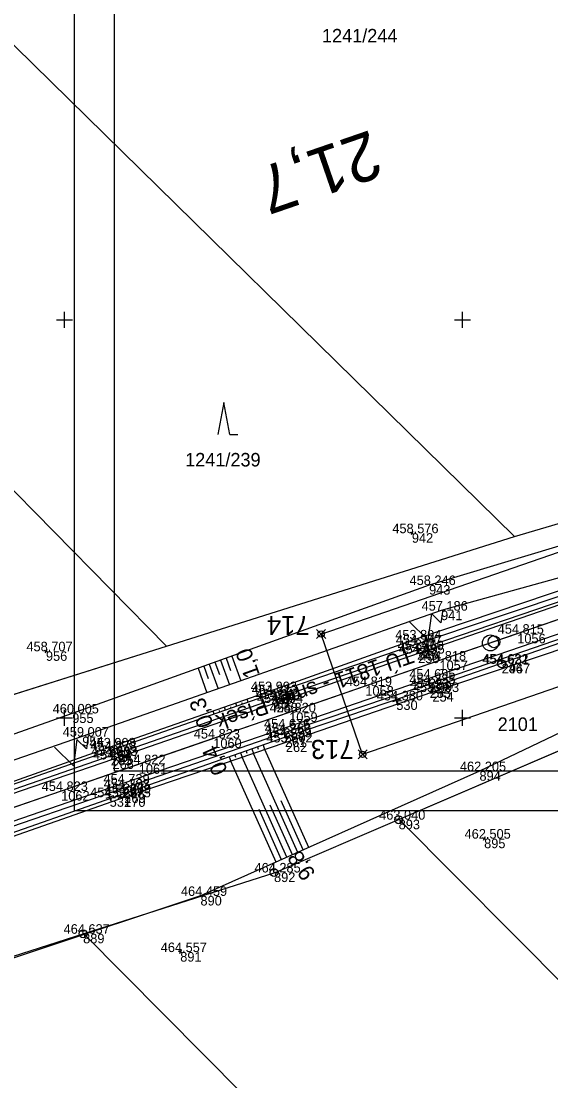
# Model space of a CAD drawing. Extents: x -776734 to -748832, y -1118122 to -976986.
# Drawn here: x -751355.4 to -751288.9, y -1114795.6 to -1114662.5 of the extents above; entities that cross this region are included whole.
import ezdxf

# ---------------------------------------------------------------- set-up
doc = ezdxf.new("R2010")
doc.units = 0
for name, color, linetype in [('KM_Hranice parcel', 7, 'Continuous'), ('KM_Parcelní čísla', 7, 'Continuous'), ('KM_Značky kultur', 7, 'Continuous'), ('Legenda 1 rámy + tabulka + severka', 7, 'Continuous'), ('Level 61 Křížky', 7, 'Continuous'), ('Obvod stavby - SŽ+ČD', 7, 'Continuous'), ('OSA', 7, 'Continuous'), ('SŽG Vrstva 1', 7, 'Continuous'), ('SŽG Vrstva 4', 7, 'Continuous'), ('SŽG Vrstva 48', 7, 'Continuous'), ('SŽG Vrstva 49', 7, 'Continuous'), ('SŽG Vrstva 50', 7, 'Continuous'), ('SŽG Vrstva 53', 7, 'Continuous'), ('SŽG Vrstva 60', 7, 'Continuous'), ('SŽG Vrstva 61', 7, 'Continuous'), ('SŽG Vrstva 7', 7, 'Continuous'), ('VYT-BODY', 7, 'Continuous')]:
    doc.layers.add(name, color=color, linetype=linetype)

msp = doc.modelspace()

# ---------------------------------------------------------------- linework, layer by layer
at = {"layer": 'KM_Hranice parcel'}
for p, q in [((-751293.44, -1114727.24), (-751406.13, -1114616.64)), ((-751439.38, -1114637.08), (-751337.18, -1114740.99)), ((-751337.18, -1114740.99), (-751293.44, -1114727.24)), ((-751377.2, -1114753.63), (-751337.18, -1114740.99)), ((-751268.46, -1114745.82), (-751307.93, -1114762.77))]:
    msp.add_line(p, q, dxfattribs=at)
for points in [[(-751293.44, -1114727.24), (-751276.39, -1114722.19), (-751236.9, -1114707.02)], [(-751307.93, -1114762.77), (-751323.57, -1114769.49), (-751347.57, -1114777.14)], [(-751307.93, -1114762.77), (-751286.55, -1114784.31), (-751238.76, -1114832.46), (-751161.13, -1114910.68), (-751116.44, -1114955.71)], [(-751347.57, -1114777.14), (-751364.44, -1114782.53), (-751398.43, -1114791.82)], [(-751126.76, -1114999.86), (-751195.24, -1114930.79), (-751259.42, -1114866.05), (-751317.55, -1114807.42), (-751347.57, -1114777.14)]]:
    msp.add_lwpolyline(points, dxfattribs=at)
at = {"layer": 'KM_Značky kultur'}
for p, q in [((-751329.9624, -1114710.4091), (-751330.7124, -1114714.4091)), ((-751329.2124, -1114714.4091), (-751329.9624, -1114710.4091)), ((-751329.2124, -1114714.4091), (-751328.2164, -1114714.4091))]:
    msp.add_line(p, q, dxfattribs=at)
at = {"layer": 'Legenda 1 rámy + tabulka + severka'}
for p, q in [((-751343.7143, -1114756.7085), (-751343.7143, -1114346.7085)), ((-751348.7143, -1114761.7085), (-751348.7143, -1114551.7085)), ((-751051.7143, -1114756.7085), (-751343.7143, -1114756.7085)), ((-751051.7143, -1114761.7085), (-751348.7143, -1114761.7085)), ((-751051.7143, -1114761.7085), (-751348.7143, -1114761.7085)), ((-751051.7143, -1114761.7085), (-751348.7143, -1114761.7085))]:
    msp.add_line(p, q, dxfattribs=at)
at = {"layer": 'Level 61 Křížky'}
for p, q in [((-751350, -1114700), (-751350, -1114699)), ((-751300, -1114700), (-751300, -1114699)), ((-751351, -1114700), (-751349, -1114700)), ((-751350, -1114701), (-751350, -1114700)), ((-751301, -1114700), (-751299, -1114700)), ((-751300, -1114701), (-751300, -1114700)), ((-751351, -1114750), (-751349, -1114750)), ((-751350, -1114750), (-751350, -1114749)), ((-751350, -1114751), (-751350, -1114750)), ((-751301, -1114750), (-751299, -1114750)), ((-751300, -1114750), (-751300, -1114749)), ((-751300, -1114751), (-751300, -1114750))]:
    msp.add_line(p, q, dxfattribs=at)
at = {"layer": 'Obvod stavby - SŽ+ČD'}
msp.add_lwpolyline([(-751172.58, -1114730.25), (-751213.65, -1114726.85), (-751218.67, -1114726.44), (-751238.9319, -1114729.2086), (-751312.5308, -1114754.601), (-751317.7491, -1114739.4759), (-751244.1502, -1114714.0835), (-751236.9, -1114707.02), (-751193.03, -1114664.28)], dxfattribs=at)
at = {"layer": 'OSA'}
for p, q in [((-751221.2446, -1114714.6435), (-751305.6868, -1114743.777)), ((-751305.6868, -1114743.777), (-751648.6661, -1114862.1099))]:
    msp.add_line(p, q, dxfattribs=at)
msp.add_circle((-751296.4756, -1114740.599), 1, dxfattribs=at)
at = {"layer": 'SŽG Vrstva 1'}
msp.add_lwpolyline([(-751207.289, -1114709.832), (-751216.509, -1114713.014), (-751226.434, -1114716.437), (-751236.324, -1114719.849), (-751245.849, -1114723.137), (-751255.285, -1114726.393), (-751264.701, -1114729.644), (-751273.956, -1114732.837), (-751283.458, -1114736.112), (-751293.108, -1114739.442), (-751302.881, -1114742.811), (-751312.192, -1114746.024), (-751321.757, -1114749.321), (-751331.295, -1114752.611), (-751340.65, -1114755.838), (-751350.401, -1114759.203), (-751359.686, -1114762.406)], dxfattribs=at)
at = {"layer": 'SŽG Vrstva 4'}
for points in [[(-751187.894, -1114700.58), (-751206.028, -1114707.041), (-751231.235, -1114715.596), (-751249.544, -1114721.971), (-751267.723, -1114728.471), (-751285.298, -1114734.541), (-751305.686, -1114741.509), (-751323.628, -1114747.668), (-751344.164, -1114754.785), (-751362.443, -1114761.123), (-751382.646, -1114767.996), (-751419.827, -1114780.907), (-751439.841, -1114787.752), (-751459.648, -1114794.565), (-751479.262, -1114801.395), (-751499.563, -1114808.301), (-751517.656, -1114814.613), (-751524.467, -1114817.135), (-751524.911, -1114817.646)], [(-751186.455, -1114705.269), (-751204.57, -1114711.262), (-751229.26, -1114719.967), (-751248.511, -1114726.389), (-751266.031, -1114732.591), (-751283.828, -1114738.73), (-751304.211, -1114745.766), (-751322.374, -1114751.898), (-751342.612, -1114758.897), (-751360.965, -1114765.168), (-751381.114, -1114772.121), (-751418.537, -1114784.997), (-751438.613, -1114791.912), (-751458.172, -1114798.656), (-751477.814, -1114805.419), (-751497.901, -1114812.476), (-751516.513, -1114818.688), (-751522.385, -1114820.606), (-751523.195, -1114820.521)], [(-751205.795, -1114707.603), (-751230.97, -1114716.264), (-751249.417, -1114722.675), (-751267.451, -1114728.869), (-751285.106, -1114734.872), (-751305.56, -1114741.936), (-751323.346, -1114748.135), (-751343.956, -1114755.234), (-751362.406, -1114761.583), (-751382.455, -1114768.543), (-751419.68, -1114781.407), (-751439.787, -1114788.305), (-751459.372, -1114795.057), (-751479.147, -1114801.881), (-751499.337, -1114808.873), (-751517.572, -1114815.159), (-751524.911, -1114817.646)], [(-751204.677, -1114710.75), (-751229.564, -1114719.281), (-751248.527, -1114725.936), (-751266.247, -1114732.037), (-751284.071, -1114738.15), (-751304.213, -1114745.084), (-751322.473, -1114751.338), (-751342.638, -1114758.269), (-751361.135, -1114764.639), (-751381.339, -1114771.707), (-751418.714, -1114784.623), (-751438.728, -1114791.466), (-751458.255, -1114798.22), (-751477.955, -1114804.997), (-751498.184, -1114811.907), (-751516.629, -1114818.238), (-751523.195, -1114820.521)]]:
    msp.add_lwpolyline(points, dxfattribs=at)
at = {"layer": 'SŽG Vrstva 48'}
for p, q in [((-751331.794, -1114743.261), (-751330.675, -1114746.371)), ((-751331.089, -1114743.007), (-751330.528, -1114744.565)), ((-751330.383, -1114742.753), (-751329.26, -1114745.874)), ((-751329.677, -1114742.499), (-751329.115, -1114744.063)), ((-751328.971, -1114742.245), (-751327.844, -1114745.377)), ((-751333.206, -1114743.769), (-751332.09, -1114746.868)), ((-751332.5, -1114743.515), (-751331.941, -1114745.067)), ((-751329.7506, -1114749.0427), (-751329.8823, -1114748.6655)), ((-751329.0425, -1114748.7954), (-751329.1084, -1114748.6068)), ((-751328.3345, -1114748.5481), (-751328.4662, -1114748.1709)), ((-751327.6264, -1114748.3009), (-751327.6923, -1114748.1123)), ((-751326.9183, -1114748.0536), (-751327.0501, -1114747.6764)), ((-751331.1667, -1114749.5373), (-751331.2985, -1114749.16)), ((-751330.4586, -1114749.29), (-751330.5245, -1114749.1014)), ((-751326.4601, -1114753.9138), (-751326.2595, -1114754.4881)), ((-751325.7521, -1114753.6665), (-751325.6507, -1114753.9568)), ((-751325.044, -1114753.4192), (-751324.8391, -1114754.0059)), ((-751319.3023, -1114766.3021), (-751324.8067, -1114753.9948)), ((-751329.2924, -1114754.903), (-751329.1004, -1114755.4526)), ((-751328.5843, -1114754.6557), (-751328.4872, -1114754.9336)), ((-751327.8762, -1114754.4084), (-751327.68, -1114754.9704)), ((-751322.0409, -1114767.5269), (-751327.6598, -1114754.9635)), ((-751327.1682, -1114754.1611), (-751327.069, -1114754.4452)), ((-751320.6716, -1114766.9145), (-751326.2333, -1114754.4792)), ((-751323.4102, -1114768.1394), (-751329.0864, -1114755.4479)), ((-751319.9869, -1114766.6083), (-751322.7535, -1114760.4227)), ((-751322.7255, -1114767.8332), (-751325.5493, -1114761.5194)), ((-751321.3562, -1114767.2207), (-751324.1514, -1114760.9711))]:
    msp.add_line(p, q, dxfattribs=at)
at = {"layer": 'SŽG Vrstva 49'}
for p, q in [((-751306.1203, -1114726.9205), (-751306.5697, -1114726.7015)), ((-751306.2355, -1114726.5863), (-751306.4545, -1114727.0357)), ((-751352.0912, -1114741.7575), (-751352.5408, -1114741.5385)), ((-751352.2065, -1114741.4232), (-751352.4255, -1114741.8728)), ((-751297.0423, -1114765.2965), (-751297.4917, -1114765.0775)), ((-751297.1575, -1114764.9623), (-751297.3765, -1114765.4117)), ((-751335.2193, -1114779.5485), (-751335.6687, -1114779.3295)), ((-751335.3345, -1114779.2143), (-751335.5535, -1114779.6637))]:
    msp.add_line(p, q, dxfattribs=at)
for points in [[(-751234.949, -1114713.279), (-751245.481, -1114717.135), (-751281.469, -1114726.527), (-751304.183, -1114733.326), (-751349.012, -1114749.456), (-751398.203, -1114766.871), (-751445.795, -1114779.905), (-751491.917, -1114801.089), (-751522.469, -1114813.154), (-751523.879, -1114811.232), (-751530.057, -1114804.525)], [(-751231.525, -1114714.481), (-751249.638, -1114721.458), (-751267.891, -1114727.816), (-751285.514, -1114733.952), (-751305.908, -1114740.796), (-751324.002, -1114747.035), (-751344.265, -1114754.112), (-751362.586, -1114760.516), (-751382.595, -1114767.438), (-751402.409, -1114774.045), (-751420.234, -1114780.2), (-751439.893, -1114787.152), (-751459.921, -1114794.045), (-751479.467, -1114800.491), (-751499.785, -1114807.5), (-751517.869, -1114814.102), (-751523.111, -1114815.97), (-751524.209, -1114815.639), (-751526.184, -1114811.436)], [(-751244.9, -1114718.575), (-751249.937, -1114720.628), (-751268.48, -1114726.929), (-751276.661, -1114729.623), (-751285.758, -1114733.326), (-751305.984, -1114740.165), (-751324.128, -1114746.656), (-751344.388, -1114753.731), (-751362.684, -1114760.234), (-751382.771, -1114766.903), (-751402.562, -1114773.563), (-751420.499, -1114779.462), (-751440.12, -1114786.635), (-751460.286, -1114793.369), (-751479.705, -1114799.993), (-751499.94, -1114807.004), (-751518.245, -1114813.43), (-751522.739, -1114814.822), (-751523.674, -1114814.114), (-751524.925, -1114811.322)], [(-751523.899, -1114821.949), (-751516.26, -1114819.366), (-751497.387, -1114813.062), (-751477.616, -1114806.13), (-751458.015, -1114799.124), (-751438.432, -1114792.474), (-751418.478, -1114785.506), (-751400.555, -1114779.532), (-751380.096, -1114772.486), (-751360.669, -1114765.898), (-751342.469, -1114759.505), (-751322.286, -1114752.456), (-751304.11, -1114746.299), (-751283.779, -1114739.207), (-751265.74, -1114733.22), (-751248.287, -1114727.037), (-751240.07, -1114724.297)], [(-751204.754, -1114724.609), (-751227.195, -1114725.505), (-751238.195, -1114726.494), (-751253.205, -1114735.378), (-751297.853, -1114756.709), (-751332.903, -1114772.385), (-751375.498, -1114786.511), (-751400.696, -1114793.558), (-751443.206, -1114803.356), (-751482.539, -1114812.284)], [(-751240.236, -1114725.654), (-751248.02, -1114728.046), (-751265.488, -1114734.037), (-751283.474, -1114739.989), (-751303.76, -1114746.769), (-751322.174, -1114753.101), (-751342.488, -1114759.998), (-751360.52, -1114766.361), (-751379.963, -1114773.044), (-751400.343, -1114780.093), (-751418.294, -1114786.259), (-751438.171, -1114793.174), (-751457.682, -1114799.957), (-751477.222, -1114807.057), (-751497.375, -1114813.972), (-751516.217, -1114820.454), (-751522.915, -1114822.926), (-751523.899, -1114821.949)], [(-751276.661, -1114729.623), (-751280.138, -1114730.299), (-751302.673, -1114736.54), (-751347.758, -1114752.369), (-751397.367, -1114769.54), (-751443.606, -1114786.702), (-751459.316, -1114792.112), (-751460.286, -1114793.369)]]:
    msp.add_lwpolyline(points, dxfattribs=at)
at = {"layer": 'SŽG Vrstva 50'}
for points in [[(-751302.469, -1114736.3918), (-751302.6888, -1114738.0544), (-751303.887, -1114736.881), (-751304.3266, -1114740.2062), (-751306.723, -1114737.8594)], [(-751347.007, -1114752.233), (-751347.227, -1114753.8955), (-751348.425, -1114752.722), (-751348.865, -1114756.0471), (-751351.2611, -1114753.7)]]:
    msp.add_lwpolyline(points, dxfattribs=at)
at = {"layer": 'SŽG Vrstva 53'}
for p, q in [((-751307.9567, -1114762.7917), (-751308.0513, -1114762.8243)), ((-751323.6127, -1114769.4227), (-751323.7073, -1114769.4553)), ((-751347.5967, -1114777.1207), (-751347.6913, -1114777.1533))]:
    msp.add_line(p, q, dxfattribs=at)
for points in [[(-751615.07, -1114840.52), (-751596.62, -1114835), (-751572.02, -1114827.5), (-751551.31, -1114808.23), (-751526.51, -1114811.39), (-751501.68, -1114801.88), (-751460.63, -1114785.23), (-751418.82, -1114768.72), (-751390.21, -1114757.9), (-751377.2, -1114753.63), (-751337.18, -1114740.99), (-751293.44, -1114727.24), (-751276.39, -1114722.19), (-751236.9, -1114707.02), (-751193.03, -1114664.28), (-751178.42, -1114675.26), (-751174.34, -1114678.03), (-751162.9, -1114674.22), (-751118.39, -1114659.47), (-751098.21, -1114652.66), (-751091.59, -1114651.24)], [(-751047.63, -1114693.52), (-751057.9, -1114691.02), (-751081.52, -1114685.27), (-751134.08, -1114703.51), (-751142.83, -1114706.54), (-751153.31, -1114710.17), (-751137.57, -1114746.06), (-751139.06, -1114746.27), (-751138.42, -1114748.17), (-751151.05, -1114751.02), (-751162.24, -1114725.26), (-751172.58, -1114730.25), (-751213.65, -1114726.85), (-751218.67, -1114726.44), (-751268.46, -1114745.82), (-751307.93, -1114762.77), (-751323.57, -1114769.49), (-751347.57, -1114777.14), (-751364.44, -1114782.53)]]:
    msp.add_lwpolyline(points, dxfattribs=at)
for centre in [(-751308.004, -1114762.808), (-751323.66, -1114769.439), (-751347.644, -1114777.137)]:
    msp.add_circle(centre, 0.4993, dxfattribs=at)
at = {"layer": 'SŽG Vrstva 60'}
for p, q in [((-751306.345, -1114726.811), (-751306.345, -1114726.811)), ((-751304.183, -1114733.326), (-751304.183, -1114733.326)), ((-751302.673, -1114736.54), (-751302.673, -1114736.54)), ((-751293.108, -1114739.442), (-751293.108, -1114739.442)), ((-751305.984, -1114740.165), (-751305.984, -1114740.165)), ((-751305.908, -1114740.796), (-751305.908, -1114740.796)), ((-751352.316, -1114741.648), (-751352.316, -1114741.648)), ((-751305.686, -1114741.509), (-751305.686, -1114741.509)), ((-751305.56, -1114741.936), (-751305.56, -1114741.936)), ((-751302.881, -1114742.811), (-751302.881, -1114742.811)), ((-751295.075, -1114743.222), (-751295.075, -1114743.222)), ((-751295.054, -1114743.207), (-751295.054, -1114743.207)), ((-751312.192, -1114746.024), (-751312.192, -1114746.024)), ((-751304.213, -1114745.084), (-751304.213, -1114745.084)), ((-751304.211, -1114745.766), (-751304.211, -1114745.766)), ((-751324.128, -1114746.656), (-751324.128, -1114746.656)), ((-751324.002, -1114747.035), (-751324.002, -1114747.035)), ((-751304.11, -1114746.299), (-751304.11, -1114746.299)), ((-751303.76, -1114746.769), (-751303.76, -1114746.769)), ((-751323.628, -1114747.668), (-751323.628, -1114747.668)), ((-751323.346, -1114748.135), (-751323.346, -1114748.135)), ((-751308.299, -1114747.817), (-751308.299, -1114747.817)), ((-751349.012, -1114749.456), (-751349.012, -1114749.456)), ((-751321.757, -1114749.321), (-751321.757, -1114749.321)), ((-751322.473, -1114751.338), (-751322.473, -1114751.338)), ((-751347.758, -1114752.369), (-751347.758, -1114752.369)), ((-751331.295, -1114752.611), (-751331.295, -1114752.611)), ((-751322.374, -1114751.898), (-751322.374, -1114751.898)), ((-751322.286, -1114752.456), (-751322.286, -1114752.456)), ((-751344.388, -1114753.731), (-751344.388, -1114753.731)), ((-751322.174, -1114753.101), (-751322.174, -1114753.101)), ((-751344.265, -1114754.112), (-751344.265, -1114754.112)), ((-751344.164, -1114754.785), (-751344.164, -1114754.785)), ((-751343.956, -1114755.234), (-751343.956, -1114755.234)), ((-751340.65, -1114755.838), (-751340.65, -1114755.838)), ((-751297.853, -1114756.709), (-751297.853, -1114756.709)), ((-751350.401, -1114759.203), (-751350.401, -1114759.203)), ((-751342.638, -1114758.269), (-751342.638, -1114758.269)), ((-751342.612, -1114758.897), (-751342.612, -1114758.897)), ((-751344.309, -1114759.981), (-751344.309, -1114759.981)), ((-751342.488, -1114759.998), (-751342.488, -1114759.998)), ((-751342.469, -1114759.505), (-751342.469, -1114759.505)), ((-751308.004, -1114762.808), (-751308.004, -1114762.808)), ((-751297.267, -1114765.187), (-751297.267, -1114765.187)), ((-751323.66, -1114769.439), (-751323.66, -1114769.439)), ((-751332.903, -1114772.385), (-751332.903, -1114772.385)), ((-751347.644, -1114777.137), (-751347.644, -1114777.137)), ((-751335.444, -1114779.439), (-751335.444, -1114779.439))]:
    msp.add_line(p, q, dxfattribs=at)
at = {"layer": 'SŽG Vrstva 7'}
for p, q in [((-751295.0277, -1114743.2057), (-751295.1223, -1114743.2383)), ((-751295.0067, -1114743.1907), (-751295.1013, -1114743.2233)), ((-751308.1359, -1114748.2897), (-751308.4621, -1114747.3443)), ((-751307.8263, -1114747.6539), (-751308.7717, -1114747.9801)), ((-751343.8364, -1114759.8179), (-751344.7816, -1114760.1441)), ((-751344.1459, -1114760.4536), (-751344.4721, -1114759.5084))]:
    msp.add_line(p, q, dxfattribs=at)
for centre, radius in [((-751296.0307, -1114740.4495), 0.75), ((-751295.075, -1114743.222), 0.5), ((-751295.054, -1114743.207), 0.5)]:
    msp.add_circle(centre, radius, dxfattribs=at)
at = {"layer": 'VYT-BODY'}
for p, q in [((-751318.3217, -1114738.9182), (-751317.1745, -1114740.0334)), ((-751317.1905, -1114738.9022), (-751318.3057, -1114740.0494)), ((-751313.1034, -1114754.0433), (-751311.9561, -1114755.1585)), ((-751311.9721, -1114754.0273), (-751313.0874, -1114755.1745))]:
    msp.add_line(p, q, dxfattribs=at)
for centre in [(-751317.7481, -1114739.4758), (-751312.5298, -1114754.6009)]:
    msp.add_circle(centre, 0.4, dxfattribs=at)

# ---------------------------------------------------------------- texts
at = {"layer": 'KM_Parcelní čísla'}
for s, p in [('1241/244', (-751317.64, -1114665.15)), ('1241/239', (-751334.8302, -1114718.4263)), ('2101', (-751295.5695, -1114751.6608))]:
    msp.add_text(s, height=1.7, dxfattribs=at).set_placement(p)
at = {"layer": 'Obvod stavby - SŽ+ČD'}
for s, p in [('714', (-751319.1928, -1114737.1949)), ('713', (-751313.6642, -1114752.7789))]:
    msp.add_text(s, height=2.4, rotation=180, dxfattribs=at).set_placement(p)
at = {"layer": 'OSA'}
for s, height, rotation, p in [('21,7', 6, 199.034988, (-751311.5347, -1114676.1011)), ('TÚ 1811 - směr Písek', 2, 199.282328, (-751306.5748, -1114741.1336))]:
    msp.add_text(s, height=height, rotation=rotation, dxfattribs=at).set_placement(p)
at = {"layer": 'SŽG Vrstva 48'}
for s, rotation, p in [('1,0', 109.789326, (-751325.418, -1114744.573)), ('0,3', 109.249726, (-751331.2519, -1114750.8235)), ('0,4', 114.251976, (-751329.4361, -1114756.6495)), ('9,8', 123.753354, (-751318.3724, -1114769.5634))]:
    msp.add_text(s, height=2, rotation=rotation, dxfattribs=at).set_placement(p)
at = {"layer": 'SŽG Vrstva 60'}
for s, p in [('942', (-751306.345, -1114728.011)), ('943', (-751304.183, -1114734.526)), ('941', (-751302.673, -1114737.74)), ('1056', (-751293.108, -1114740.642)), ('247', (-751305.984, -1114741.365)), ('248', (-751305.908, -1114741.996)), ('956', (-751352.316, -1114742.848)), ('249', (-751305.686, -1114742.709)), ('250', (-751305.56, -1114743.136)), ('1057', (-751302.881, -1114744.011)), ('246', (-751295.075, -1114744.422)), ('2947', (-751295.054, -1114744.407)), ('1058', (-751312.192, -1114747.224)), ('251', (-751304.213, -1114746.284)), ('252', (-751304.211, -1114746.966)), ('255', (-751324.128, -1114747.856)), ('256', (-751324.002, -1114748.235)), ('253', (-751304.11, -1114747.499)), ('254', (-751303.76, -1114747.969)), ('257', (-751323.628, -1114748.868)), ('258', (-751323.346, -1114749.335)), ('530', (-751308.299, -1114749.017)), ('955', (-751349.012, -1114750.656)), ('1059', (-751321.757, -1114750.521)), ('259', (-751322.473, -1114752.538)), ('954', (-751347.758, -1114753.569)), ('1060', (-751331.295, -1114753.811)), ('260', (-751322.374, -1114753.098)), ('261', (-751322.286, -1114753.656)), ('263', (-751344.388, -1114754.931)), ('264', (-751344.265, -1114755.312)), ('262', (-751322.174, -1114754.301)), ('265', (-751344.164, -1114755.985)), ('266', (-751343.956, -1114756.434)), ('1061', (-751340.65, -1114757.038)), ('894', (-751297.853, -1114757.909)), ('1062', (-751350.401, -1114760.403)), ('267', (-751342.638, -1114759.469)), ('268', (-751342.612, -1114760.097)), ('531', (-751344.309, -1114761.181)), ('270', (-751342.488, -1114761.198)), ('269', (-751342.469, -1114760.705)), ('893', (-751308.004, -1114764.008)), ('895', (-751297.267, -1114766.387)), ('892', (-751323.66, -1114770.639)), ('890', (-751332.903, -1114773.585)), ('889', (-751347.644, -1114778.337)), ('891', (-751335.444, -1114780.639))]:
    msp.add_text(s, height=1.2, dxfattribs=at).set_placement(p)
at = {"layer": 'SŽG Vrstva 61'}
for s, p in [('458.576', (-751308.7969, -1114726.811)), ('458.246', (-751306.6349, -1114733.326)), ('457.186', (-751305.1249, -1114736.54)), ('453.894', (-751308.435, -1114740.165)), ('454.815', (-751295.5641, -1114739.442)), ('458.707', (-751354.7679, -1114741.648)), ('454.247', (-751308.3599, -1114740.796)), ('454.360', (-751308.137, -1114741.509)), ('454.695', (-751308.0161, -1114741.936)), ('454.818', (-751305.3347, -1114742.811)), ('454.622', (-751297.5022, -1114743.207)), ('454.631', (-751297.4324, -1114743.222)), ('454.695', (-751306.6691, -1114745.084)), ('454.235', (-751306.6671, -1114745.766)), ('453.993', (-751326.5799, -1114746.656)), ('454.313', (-751326.4539, -1114747.035)), ('454.819', (-751314.6457, -1114746.024)), ('454.237', (-751306.5619, -1114746.299)), ('453.893', (-751306.2119, -1114746.769)), ('454.361', (-751325.9854, -1114747.668)), ('454.694', (-751325.797, -1114748.135)), ('454.380', (-751310.75, -1114747.817)), ('460.005', (-751351.4681, -1114749.456)), ('454.820', (-751324.208, -1114749.321)), ('459.007', (-751350.2099, -1114752.369)), ('454.823', (-751333.7469, -1114752.611)), ('454.676', (-751324.9249, -1114751.338)), ('454.260', (-751324.825, -1114751.898)), ('454.239', (-751324.7397, -1114752.456)), ('453.908', (-751346.8417, -1114753.731)), ('453.872', (-751324.6222, -1114753.101)), ('454.278', (-751346.7187, -1114754.112)), ('454.303', (-751346.6159, -1114754.785)), ('454.627', (-751346.4079, -1114755.234)), ('454.822', (-751343.0982, -1114755.838)), ('462.205', (-751300.3091, -1114756.709)), ('454.823', (-751352.8529, -1114759.203)), ('454.739', (-751345.0917, -1114758.269)), ('454.303', (-751345.0639, -1114758.897)), ('454.523', (-751346.7609, -1114759.981)), ('453.975', (-751344.9441, -1114759.998)), ('454.269', (-751344.9227, -1114759.505)), ('463.040', (-751310.455, -1114762.808)), ('462.505', (-751299.7231, -1114765.187)), ('464.285', (-751326.1161, -1114769.439)), ('464.459', (-751335.3567, -1114772.385)), ('464.637', (-751350.0959, -1114777.137)), ('464.557', (-751337.8959, -1114779.439))]:
    msp.add_text(s, height=1.2, dxfattribs=at).set_placement(p)

doc.saveas('drawing.dxf')
